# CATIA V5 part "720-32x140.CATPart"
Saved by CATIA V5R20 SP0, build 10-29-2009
Part number: 720-32x140
Definition: NONE
Nomenclature: 720-32x140
Source: Unknown
Description: 720-32x140
Bounding box of the stored display mesh (mm): x 0 to 140, y -16 to 16, z -16 to 16
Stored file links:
  C:\Users\Utente\Desktop\IO LAVORO\3D X SITO CF\X SITO\720\720-32x140.CATPart

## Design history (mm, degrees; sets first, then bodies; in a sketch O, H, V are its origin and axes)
Body1 "720-32x140" (main body)
  Solid1: solid without history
